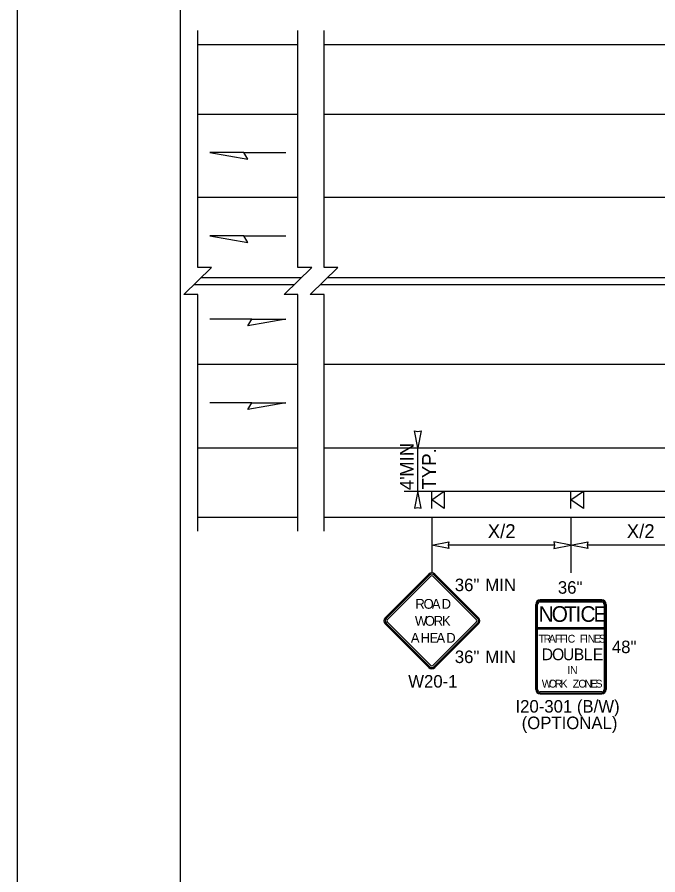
# Model space of a CAD drawing. Extents: x 99999.1 to 100096.1, y 99995 to 100010.7.
# Drawn here: x 100019.062 to 100022.749, y 100002.928 to 100007.863 of the extents above; entities that cross this region are included whole.
import ezdxf

# ---------------------------------------------------------------- set-up
doc = ezdxf.new("R2010")
doc.units = 0
for name, color, linetype in [('RD_ED_ShoulderPavedEdge', 7, 'Continuous'), ('RD_MK_LineDblYellowCenter', 7, 'Continuous'), ('RD_MK_LineEdgeWhite', 7, 'Continuous'), ('RD_MK_LineLane', 7, 'Continuous'), ('SH_GI_PlotLimits', 7, 'Continuous'), ('SH_GI_SheetBorder', 7, 'Continuous'), ('TR_SN_ConstructionSigns', 7, 'Continuous'), ('TR_WZ_PortableSignMountBlk-Org', 7, 'Continuous'), ('TR_WZ_PortableSignMountBlk-Wht', 7, 'Continuous'), ('TR_WZ_WorkZoneDetails', 7, 'Continuous'), ('TR_WZ_WorkZoneTextCurrent', 7, 'Continuous')]:
    doc.layers.add(name, color=color, linetype=linetype)

msp = doc.modelspace()

# ---------------------------------------------------------------- linework, layer by layer
at = {"layer": 'RD_ED_ShoulderPavedEdge'}
for p, q in [((100020.1016, 100007.7057), (100020.6783, 100007.7057)), ((100020.8283, 100007.7057), (100034.8933, 100007.7057)), ((100020.1016, 100004.9857), (100020.6783, 100004.9857)), ((100020.8283, 100004.9857), (100034.8933, 100004.9857))]:
    msp.add_line(p, q, dxfattribs=at)
at = {"layer": 'RD_MK_LineDblYellowCenter'}
for p, q in [((100020.1223, 100006.3657), (100020.699, 100006.3657)), ((100020.849, 100006.3657), (100034.914, 100006.3657)), ((100020.081, 100006.3257), (100020.6576, 100006.3257)), ((100020.8076, 100006.3257), (100034.8726, 100006.3257))]:
    msp.add_line(p, q, dxfattribs=at)
at = {"layer": 'RD_MK_LineEdgeWhite'}
for p, q in [((100020.1016, 100007.3057), (100020.6783, 100007.3057)), ((100020.8283, 100007.3057), (100034.8933, 100007.3057)), ((100020.1016, 100005.3857), (100020.6783, 100005.3857)), ((100020.8283, 100005.3857), (100034.8933, 100005.3857))]:
    msp.add_line(p, q, dxfattribs=at)
at = {"layer": 'RD_MK_LineLane'}
for points in [[(100020.6783, 100006.8257), (100020.1016, 100006.8257)], [(100034.8933, 100006.8257), (100020.8283, 100006.8257)], [(100020.6783, 100005.8657), (100020.1016, 100005.8657)], [(100034.8933, 100005.8657), (100020.8283, 100005.8657)]]:
    msp.add_lwpolyline(points, dxfattribs=at)
at = {"layer": 'SH_GI_PlotLimits'}
msp.add_lwpolyline([(100019.0625, 99999.6875), (100036.0625, 99999.6875), (100036.0625, 100010.6875), (100019.0625, 100010.6875)], close=True, dxfattribs=at)
at = {"layer": 'SH_GI_SheetBorder'}
msp.add_line((100020, 100010.375), (100020, 100000), dxfattribs=at)
at = {"layer": 'TR_SN_ConstructionSigns'}
for p, q in [((100021.4307, 100004.6583), (100021.1801, 100004.4077)), ((100021.4357, 100004.6533), (100021.1851, 100004.4028)), ((100021.1921, 100004.3958), (100021.4426, 100004.6464)), ((100021.4546, 100004.6464), (100021.7052, 100004.3958)), ((100021.7121, 100004.4028), (100021.4615, 100004.6533)), ((100021.7171, 100004.4077), (100021.4665, 100004.6583)), ((100022.0714, 100004.51), (100022.4258, 100004.51)), ((100022.4258, 100004.51), (100022.0714, 100004.51)), ((100022.4258, 100004.51), (100022.0714, 100004.51)), ((100022.4258, 100004.5058), (100022.0714, 100004.5058)), ((100022.0714, 100004.4988), (100022.4258, 100004.4988)), ((100022.0461, 100003.9953), (100022.0461, 100004.4847)), ((100022.0461, 100004.4847), (100022.0461, 100003.9953)), ((100022.0461, 100004.4847), (100022.0461, 100003.9953)), ((100022.0503, 100004.4847), (100022.0503, 100003.9953)), ((100022.0574, 100004.3504), (100022.0574, 100004.4847)), ((100022.4399, 100004.4847), (100022.4399, 100004.3504)), ((100022.4469, 100003.9953), (100022.4469, 100004.4847)), ((100022.4511, 100004.4847), (100022.4511, 100003.9953)), ((100022.4511, 100003.9953), (100022.4511, 100004.4847)), ((100022.4511, 100003.9953), (100022.4511, 100004.4847)), ((100021.1801, 100004.3719), (100021.4307, 100004.1214)), ((100021.1851, 100004.3769), (100021.4357, 100004.1263)), ((100021.4426, 100004.1333), (100021.1921, 100004.3839)), ((100021.7052, 100004.3839), (100021.4546, 100004.1333)), ((100021.4615, 100004.1263), (100021.7121, 100004.3769)), ((100021.4665, 100004.1214), (100021.7171, 100004.3719)), ((100022.0574, 100004.3504), (100022.0574, 100004.3504)), ((100022.4399, 100004.3504), (100022.0574, 100004.3504)), ((100022.0574, 100004.3504), (100022.0574, 100004.3434)), ((100022.0574, 100004.3434), (100022.0574, 100004.3504)), ((100022.0574, 100004.3434), (100022.4399, 100004.3434)), ((100022.0574, 100003.9953), (100022.0574, 100004.3434)), ((100022.4399, 100004.3434), (100022.4399, 100004.3504)), ((100022.4399, 100004.3504), (100022.4399, 100004.3434)), ((100022.4399, 100004.3434), (100022.4399, 100003.9953)), ((100022.4258, 100003.9813), (100022.0714, 100003.9813)), ((100022.0714, 100003.9742), (100022.4258, 100003.9742)), ((100022.4258, 100003.97), (100022.0714, 100003.97)), ((100022.0714, 100003.97), (100022.4258, 100003.97)), ((100022.0714, 100003.97), (100022.4258, 100003.97))]:
    msp.add_line(p, q, dxfattribs=at)
for centre, radius, start, end in [((100021.4486, 100004.6404), 0.0253, 45, 135), ((100021.4486, 100004.6404), 0.0183, 45, 135), ((100021.4486, 100004.6404), 0.00844, 45, 135), ((100022.0714, 100004.4847), 0.0253, 90, 180), ((100022.0714, 100004.4847), 0.0253, 90, 180), ((100022.0714, 100004.4847), 0.0253, 90, 180), ((100022.0714, 100004.4847), 0.0211, 90, 180), ((100022.0714, 100004.4847), 0.0141, 90, 180), ((100022.4258, 100004.4847), 0.0253, 0, 90), ((100022.4258, 100004.4847), 0.0253, 0, 90), ((100022.4258, 100004.4847), 0.0253, 0, 90), ((100022.4258, 100004.4847), 0.0211, 0, 90), ((100022.4258, 100004.4847), 0.0141, 0, 90), ((100021.198, 100004.3898), 0.0253, 135, 225), ((100021.198, 100004.3898), 0.0183, 135, 225), ((100021.198, 100004.3898), 0.00844, 135, 225), ((100021.6992, 100004.3898), 0.00844, 315, 45), ((100021.6992, 100004.3898), 0.0183, 315, 45), ((100021.6992, 100004.3898), 0.0253, 315, 45), ((100021.4486, 100004.1393), 0.0253, 225, 315), ((100021.4486, 100004.1393), 0.0183, 225, 315), ((100021.4486, 100004.1393), 0.00844, 225, 315), ((100022.0714, 100003.9953), 0.0253, 180, 270), ((100022.0714, 100003.9953), 0.0253, 180, 270), ((100022.0714, 100003.9953), 0.0253, 180, 270), ((100022.0714, 100003.9953), 0.0211, 180, 270), ((100022.0714, 100003.9953), 0.0141, 180, 270), ((100022.4258, 100003.9953), 0.0253, 270, 0), ((100022.4258, 100003.9953), 0.0253, 270, 0), ((100022.4258, 100003.9953), 0.0211, 270, 0), ((100022.4258, 100003.9953), 0.0141, 270, 0), ((100022.4258, 100003.9953), 0.0253, 270, 0)]:
    msp.add_arc(centre, radius, start, end, dxfattribs=at)
at = {"layer": 'TR_WZ_PortableSignMountBlk-Org'}
msp.add_line((100021.4486, 100005.0358), (100021.4486, 100005.1358), dxfattribs=at)
msp.add_lwpolyline([(100021.4486, 100005.0857), (100021.5204, 100005.1358), (100021.5204, 100005.0358)], close=True, dxfattribs=at)
at = {"layer": 'TR_WZ_PortableSignMountBlk-Wht'}
msp.add_line((100022.2486, 100005.0357), (100022.2486, 100005.1357), dxfattribs=at)
msp.add_lwpolyline([(100022.2486, 100005.0856), (100022.3204, 100005.1357), (100022.3204, 100005.0357)], close=True, dxfattribs=at)
at = {"layer": 'TR_WZ_WorkZoneDetails'}
for p, q in [((100020.3677, 100007.085), (100020.6088, 100007.085)), ((100020.3677, 100006.605), (100020.6088, 100006.605)), ((100020.4123, 100006.125), (100020.1712, 100006.125)), ((100020.4123, 100005.645), (100020.1712, 100005.645)), ((100021.2886, 100005.3857), (100021.4486, 100005.3857)), ((100021.3686, 100005.1358), (100021.3686, 100005.3857)), ((100021.2886, 100005.1358), (100021.4486, 100005.1358)), ((100021.4486, 100005.1358), (100025.9101, 100005.1358)), ((100021.4486, 100004.9857), (100021.4486, 100004.6657)), ((100022.2486, 100004.986), (100022.2486, 100004.6657)), ((100022.1549, 100004.8257), (100021.5423, 100004.8257)), ((100022.9549, 100004.8257), (100022.3423, 100004.8257))]:
    msp.add_line(p, q, dxfattribs=at)
for points in [[(100020.1016, 100004.9057), (100020.1016, 100006.2683), (100020.0216, 100006.2683), (100020.1817, 100006.4232), (100020.1016, 100006.4232), (100020.1016, 100007.7857)], [(100020.6783, 100004.9057), (100020.6783, 100006.2683), (100020.5983, 100006.2683), (100020.7583, 100006.4232), (100020.6783, 100006.4232), (100020.6783, 100007.7857)], [(100020.8283, 100004.9057), (100020.8283, 100006.2683), (100020.7483, 100006.2683), (100020.9083, 100006.4232), (100020.8283, 100006.4232), (100020.8283, 100007.7857)]]:
    msp.add_lwpolyline(points, dxfattribs=at)
for points in [[(100020.1712, 100007.085), (100020.39, 100007.0464), (100020.3677, 100007.085)], [(100020.1712, 100006.605), (100020.39, 100006.5664), (100020.3677, 100006.605)], [(100020.6088, 100006.125), (100020.39, 100006.0864), (100020.4123, 100006.125)], [(100020.6088, 100005.645), (100020.39, 100005.6064), (100020.4123, 100005.645)], [(100021.3686, 100005.3857), (100021.3493, 100005.484), (100021.3686, 100005.4795), (100021.3879, 100005.484)], [(100021.3686, 100005.1358), (100021.3493, 100005.0375), (100021.3686, 100005.0421), (100021.3879, 100005.0375)], [(100021.4486, 100004.8257), (100021.5469, 100004.845), (100021.5423, 100004.8257), (100021.5469, 100004.8065)], [(100022.2486, 100004.8257), (100022.1503, 100004.845), (100022.1549, 100004.8257), (100022.1503, 100004.8065)], [(100022.2486, 100004.8257), (100022.3469, 100004.845), (100022.3423, 100004.8257), (100022.3469, 100004.8065)]]:
    msp.add_lwpolyline(points, close=True, dxfattribs=at)

# ---------------------------------------------------------------- texts
at = {"layer": 'TR_SN_ConstructionSigns'}
for s, p in [('36"', (100021.5807, 100004.5607)), ('MIN', (100021.7562, 100004.5607)), ('36"', (100022.1738, 100004.546)), ('48"', (100022.4844, 100004.204)), ('36"', (100021.5807, 100004.147)), ('MIN', (100021.7562, 100004.147)), ('W20-1', (100021.3128, 100004.0059)), ('I20-301 (B/W)', (100021.93, 100003.862)), ('(OPTIONAL)', (100021.9655, 100003.7669))]:
    msp.add_text(s, height=0.072, rotation=360, dxfattribs=at).set_placement(p)
for s, height, p in [('R', 0.0562, (100021.354, 100004.4594)), ('O', 0.0562, (100021.401, 100004.4594)), ('A', 0.0562, (100021.4484, 100004.4594)), ('D', 0.0562, (100021.5049, 100004.4594)), ('N', 0.09, (100022.0629, 100004.3842)), ('O', 0.09, (100022.1379, 100004.3842)), ('T', 0.09, (100022.21, 100004.3842)), ('I', 0.09, (100022.2753, 100004.3842)), ('C', 0.09, (100022.3035, 100004.3842)), ('E', 0.09, (100022.3786, 100004.3842)), ('W', 0.0562, (100021.3511, 100004.3617)), ('O', 0.0562, (100021.408, 100004.3617)), ('R', 0.0562, (100021.4595, 100004.3617)), ('K', 0.0562, (100021.5067, 100004.3617)), ('A', 0.0562, (100021.3277, 100004.264)), ('H', 0.0562, (100021.3839, 100004.264)), ('E', 0.0562, (100021.4357, 100004.264)), ('A', 0.0562, (100021.4751, 100004.264)), ('D', 0.0562, (100021.5313, 100004.264)), ('T', 0.045, (100022.0628, 100004.2646)), ('R', 0.045, (100022.092, 100004.2646)), ('A', 0.045, (100022.1213, 100004.2646)), ('F', 0.045, (100022.1564, 100004.2646)), ('F', 0.045, (100022.1856, 100004.2646)), ('I', 0.045, (100022.2149, 100004.2646)), ('C', 0.045, (100022.2302, 100004.2646)), ('F', 0.045, (100022.3004, 100004.2646)), ('I', 0.045, (100022.3296, 100004.2646)), ('N', 0.045, (100022.3458, 100004.2646)), ('E', 0.045, (100022.3809, 100004.2646)), ('S', 0.045, (100022.4093, 100004.2646)), ('D', 0.0675, (100022.0809, 100004.1634)), ('O', 0.0675, (100022.1403, 100004.1634)), ('U', 0.0675, (100022.2031, 100004.1634)), ('B', 0.0675, (100022.2652, 100004.1634)), ('L', 0.0675, (100022.3225, 100004.1634)), ('E', 0.0675, (100022.3745, 100004.1634)), ('I', 0.045, (100022.2279, 100004.0846)), ('N', 0.045, (100022.2441, 100004.0846)), ('W', 0.045, (100022.0814, 100004.0059)), ('O', 0.045, (100022.121, 100004.0059)), ('R', 0.045, (100022.1566, 100004.0059)), ('K', 0.045, (100022.1894, 100004.0059)), ('Z', 0.045, (100022.2596, 100004.0059)), ('O', 0.045, (100022.2916, 100004.0059)), ('N', 0.045, (100022.3271, 100004.0059)), ('E', 0.045, (100022.3622, 100004.0059)), ('S', 0.045, (100022.3906, 100004.0059))]:
    msp.add_text(s, height=height, dxfattribs=at).set_placement(p)
at = {"layer": 'TR_WZ_WorkZoneTextCurrent'}
for s, rotation, p in [('MIN', 90, (100021.3446, 100005.2182)), ('TYP.', 90, (100021.4726, 100005.1454)), ("4'", 90, (100021.3446, 100005.1417)), ('X/2', 360, (100021.7701, 100004.8657)), ('X/2', 360, (100022.5701, 100004.8657))]:
    msp.add_text(s, height=0.08, rotation=rotation, dxfattribs=at).set_placement(p)

doc.saveas('drawing.dxf')
